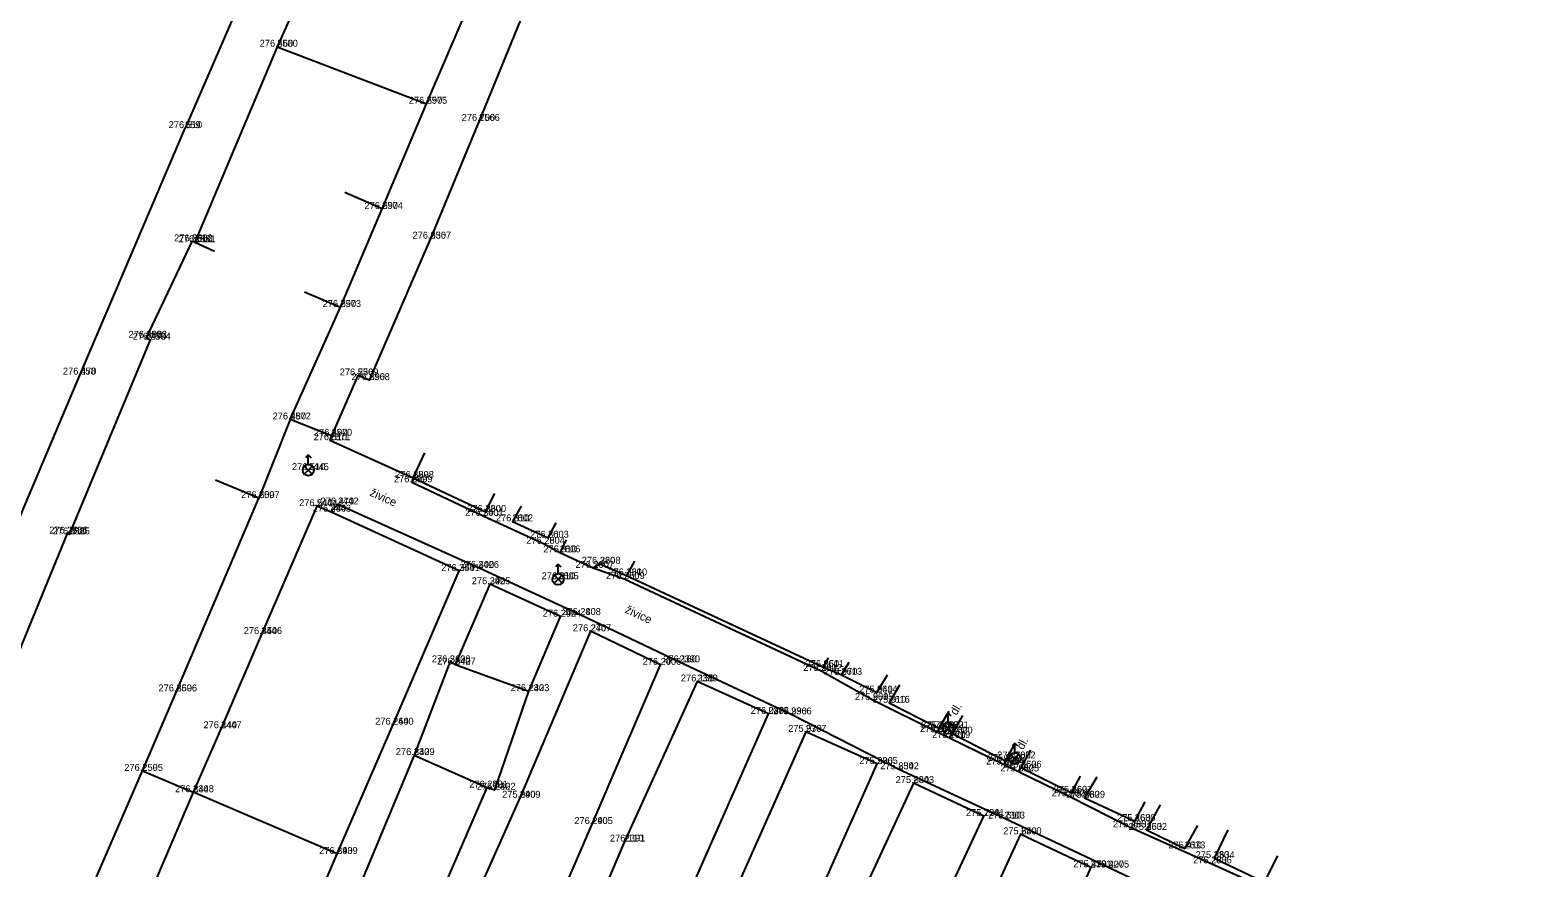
# Model space of a CAD drawing. Extents: x -776701 to -776081, y -974398 to -973771.
# Drawn here: x -776453.1 to -776398.7, y -974133.8 to -974103.6 of the extents above; entities that cross this region are included whole.
import ezdxf

# ---------------------------------------------------------------- set-up
doc = ezdxf.new("R2010")
doc.units = 0
for name, color, linetype in [('1 Body-bod', 7, 'Continuous'), ('10 Silnice-chodniky', 7, 'Continuous'), ('11 Rozhrani-nezpev zpev schody', 7, 'Continuous'), ('2 Body-cislo', 7, 'Continuous'), ('3 Body-vyska', 7, 'Continuous'), ('40 Popis-povrch', 7, 'Continuous'), ('58 Mobiliar', 7, 'Continuous'), ('7 Ploty', 7, 'Continuous')]:
    doc.layers.add(name, color=color, linetype=linetype)

msp = doc.modelspace()

# ---------------------------------------------------------------- linework, layer by layer
at = {"layer": '1 Body-bod'}
for p, q in [((-776444.22, -974104.18), (-776444.22, -974104.18)), ((-776438.83, -974106.24), (-776438.83, -974106.24)), ((-776436.93, -974106.86), (-776436.93, -974106.86)), ((-776447.55, -974107.12), (-776447.55, -974107.12)), ((-776440.43, -974110.04), (-776440.43, -974110.04)), ((-776447.3, -974111.21), (-776447.3, -974111.21)), ((-776447.19, -974111.24), (-776447.19, -974111.24)), ((-776438.69, -974111.11), (-776438.69, -974111.11)), ((-776441.94, -974113.58), (-776441.94, -974113.58)), ((-776448.95, -974114.69), (-776448.95, -974114.69)), ((-776448.81, -974114.76), (-776448.81, -974114.76)), ((-776451.33, -974116.02), (-776451.33, -974116.02)), ((-776441.31, -974116.05), (-776441.31, -974116.05)), ((-776440.9, -974116.22), (-776440.9, -974116.22)), ((-776443.75, -974117.64), (-776443.75, -974117.64)), ((-776442.26, -974118.23), (-776442.26, -974118.23)), ((-776442.32, -974118.39), (-776442.32, -974118.39)), ((-776443.1, -974119.47), (-776443.1, -974119.47)), ((-776439.36, -974119.91), (-776439.36, -974119.91)), ((-776439.31, -974119.75), (-776439.31, -974119.75)), ((-776444.88, -974120.48), (-776444.88, -974120.48)), ((-776442.79, -974120.77), (-776442.79, -974120.77)), ((-776442.3, -974120.97), (-776442.3, -974120.97)), ((-776442.03, -974120.71), (-776442.03, -974120.71)), ((-776436.7, -974120.98), (-776436.7, -974120.98)), ((-776436.79, -974121.12), (-776436.79, -974121.12)), ((-776435.73, -974121.32), (-776435.73, -974121.32)), ((-776451.81, -974121.76), (-776451.81, -974121.76)), ((-776451.73, -974121.79), (-776451.73, -974121.79)), ((-776434.58, -974122.13), (-776434.58, -974122.13)), ((-776434.44, -974121.91), (-776434.44, -974121.91)), ((-776434.02, -974122.44), (-776434.02, -974122.44)), ((-776437.65, -974123.11), (-776437.65, -974123.11)), ((-776436.96, -974123), (-776436.96, -974123)), ((-776432.81, -974123), (-776432.81, -974123)), ((-776432.57, -974122.85), (-776432.57, -974122.85)), ((-776436.55, -974123.59), (-776436.55, -974123.59)), ((-776434.08, -974123.41), (-776434.08, -974123.41)), ((-776431.7, -974123.4), (-776431.7, -974123.4)), ((-776431.61, -974123.27), (-776431.61, -974123.27)), ((-776433.99, -974124.76), (-776433.99, -974124.76)), ((-776433.28, -974124.7), (-776433.28, -974124.7)), ((-776444.79, -974125.39), (-776444.79, -974125.39)), ((-776432.91, -974125.29), (-776432.91, -974125.29)), ((-776437.99, -974126.41), (-776437.99, -974126.41)), ((-776437.8, -974126.49), (-776437.8, -974126.49)), ((-776430.38, -974126.5), (-776430.38, -974126.5)), ((-776429.7, -974126.41), (-776429.7, -974126.41)), ((-776424.58, -974126.72), (-776424.58, -974126.72)), ((-776424.5, -974126.58), (-776424.5, -974126.58)), ((-776423.85, -974126.86), (-776423.85, -974126.86)), ((-776447.86, -974127.46), (-776447.86, -974127.46)), ((-776435.14, -974127.45), (-776435.14, -974127.45)), ((-776429.06, -974127.1), (-776429.06, -974127.1)), ((-776422.57, -974127.5), (-776422.57, -974127.5)), ((-776422.72, -974127.77), (-776422.72, -974127.77)), ((-776422.13, -974127.87), (-776422.13, -974127.87)), ((-776440.04, -974128.66), (-776440.04, -974128.66)), ((-776426.49, -974128.27), (-776426.49, -974128.27)), ((-776425.67, -974128.29), (-776425.67, -974128.29)), ((-776446.25, -974128.79), (-776446.25, -974128.79)), ((-776425.14, -974128.92), (-776425.14, -974128.92)), ((-776420.37, -974128.93), (-776420.37, -974128.93)), ((-776420.33, -974128.79), (-776420.33, -974128.79)), ((-776420, -974128.79), (-776420, -974128.79)), ((-776419.95, -974129.14), (-776419.95, -974129.14)), ((-776419.86, -974128.98), (-776419.86, -974128.98)), ((-776439.28, -974129.76), (-776439.28, -974129.76)), ((-776422.56, -974130.08), (-776422.56, -974130.08)), ((-776421.8, -974130.27), (-776421.8, -974130.27)), ((-776417.98, -974130.1), (-776417.98, -974130.1)), ((-776417.93, -974129.97), (-776417.93, -974129.97)), ((-776417.59, -974129.88), (-776417.59, -974129.88)), ((-776417.37, -974130.21), (-776417.37, -974130.21)), ((-776449.09, -974130.33), (-776449.09, -974130.33)), ((-776421.25, -974130.77), (-776421.25, -974130.77)), ((-776417.46, -974130.35), (-776417.46, -974130.35)), ((-776447.25, -974131.1), (-776447.25, -974131.1)), ((-776436.64, -974130.93), (-776436.64, -974130.93)), ((-776436.36, -974131.01), (-776436.36, -974131.01)), ((-776435.46, -974131.3), (-776435.46, -974131.3)), ((-776415.61, -974131.25), (-776415.61, -974131.25)), ((-776415.54, -974131.12), (-776415.54, -974131.12)), ((-776415.08, -974131.3), (-776415.08, -974131.3)), ((-776432.85, -974132.25), (-776432.85, -974132.25)), ((-776418.71, -974131.96), (-776418.71, -974131.96)), ((-776417.97, -974132.05), (-776417.97, -974132.05)), ((-776413.4, -974132.37), (-776413.4, -974132.37)), ((-776413.26, -974132.14), (-776413.26, -974132.14)), ((-776412.84, -974132.46), (-776412.84, -974132.46)), ((-776431.68, -974132.88), (-776431.68, -974132.88)), ((-776417.37, -974132.62), (-776417.37, -974132.62)), ((-776442.06, -974133.33), (-776442.06, -974133.33)), ((-776411.46, -974133.13), (-776411.46, -974133.13)), ((-776410.4, -974133.48), (-776410.4, -974133.48)), ((-776414.85, -974133.81), (-776414.85, -974133.81)), ((-776414.21, -974133.82), (-776414.21, -974133.82)), ((-776410.5, -974133.67), (-776410.5, -974133.67))]:
    msp.add_line(p, q, dxfattribs=at)
at = {"layer": '10 Silnice-chodniky'}
msp.add_line((-776449.09, -974130.33), (-776447.25, -974131.1), dxfattribs=at)
for points in [[(-776442.26, -974118.23), (-776443.75, -974117.64), (-776444.88, -974120.48)], [(-776439.31, -974119.75), (-776439.36, -974119.91), (-776436.79, -974121.12), (-776434.58, -974122.13), (-776434.02, -974122.44)], [(-776398.71, -974141.07), (-776402.53, -974139.28), (-776406.41, -974137.48), (-776410.27, -974135.71), (-776414.21, -974133.82), (-776417.97, -974132.05), (-776421.8, -974130.27), (-776425.67, -974128.29), (-776429.7, -974126.41), (-776433.28, -974124.7), (-776436.96, -974123), (-776442.03, -974120.71), (-776442.3, -974120.97)], [(-776432.81, -974123), (-776431.7, -974123.4), (-776424.58, -974126.72), (-776422.72, -974127.77), (-776420.37, -974128.93), (-776419.95, -974129.14), (-776417.98, -974130.1), (-776417.46, -974130.35), (-776415.61, -974131.25), (-776413.4, -974132.37), (-776410.5, -974133.67), (-776408.14, -974134.74), (-776403.96, -974136.76), (-776401.68, -974137.82), (-776401.22, -974137.88)], [(-776420.33, -974128.79), (-776420.37, -974128.93)], [(-776419.95, -974129.14), (-776419.86, -974128.98)], [(-776417.93, -974129.97), (-776417.98, -974130.1)], [(-776417.46, -974130.35), (-776417.37, -974130.21)]]:
    msp.add_lwpolyline(points, dxfattribs=at)
at = {"layer": '11 Rozhrani-nezpev zpev schody'}
for points in [[(-776443.75, -974117.64), (-776441.94, -974113.58)], [(-776431.32, -974122.762), (-776431.61, -974123.27), (-776424.5, -974126.58), (-776424.32, -974126.245)]]:
    msp.add_lwpolyline(points, dxfattribs=at)
at = {"layer": '58 Mobiliar'}
for p, q in [((-776443.1, -974119.47), (-776443.243, -974119.328)), ((-776443.1, -974118.92), (-776443.2, -974119.02)), ((-776443.1, -974119.269), (-776443.1, -974118.92)), ((-776443.1, -974118.92), (-776443, -974119.02)), ((-776443.1, -974119.47), (-776442.958, -974119.328)), ((-776443.1, -974119.47), (-776443.243, -974119.613)), ((-776443.1, -974119.47), (-776443.1, -974119.47)), ((-776443.1, -974119.47), (-776442.958, -974119.613)), ((-776434.08, -974122.86), (-776434.18, -974122.96)), ((-776434.08, -974123.209), (-776434.08, -974122.86)), ((-776434.08, -974122.86), (-776433.98, -974122.96)), ((-776434.08, -974123.41), (-776434.223, -974123.268)), ((-776434.08, -974123.41), (-776434.223, -974123.552)), ((-776434.08, -974123.41), (-776433.938, -974123.268)), ((-776434.08, -974123.41), (-776434.08, -974123.41)), ((-776434.08, -974123.41), (-776433.938, -974123.552)), ((-776420, -974128.79), (-776420.142, -974128.647)), ((-776420, -974128.24), (-776420.1, -974128.34)), ((-776420, -974128.589), (-776420, -974128.24)), ((-776420, -974128.24), (-776419.9, -974128.34)), ((-776420, -974128.79), (-776419.858, -974128.647)), ((-776420, -974128.79), (-776420.142, -974128.932)), ((-776420, -974128.79), (-776420, -974128.79)), ((-776420, -974128.79), (-776419.858, -974128.932)), ((-776417.59, -974129.88), (-776417.733, -974129.738)), ((-776417.59, -974129.33), (-776417.69, -974129.43)), ((-776417.59, -974129.679), (-776417.59, -974129.33)), ((-776417.59, -974129.33), (-776417.49, -974129.43)), ((-776417.59, -974129.88), (-776417.448, -974129.738)), ((-776417.59, -974129.88), (-776417.733, -974130.022)), ((-776417.59, -974129.88), (-776417.59, -974129.88)), ((-776417.59, -974129.88), (-776417.448, -974130.022))]:
    msp.add_line(p, q, dxfattribs=at)
for centre in [(-776443.1, -974119.47), (-776434.08, -974123.41), (-776420, -974128.79), (-776417.59, -974129.88)]:
    msp.add_circle(centre, 0.202, dxfattribs=at)
at = {"layer": '7 Ploty'}
for p, q in [((-776444.22, -974104.18), (-776438.83, -974106.24)), ((-776440.43, -974110.04), (-776441.781, -974109.444)), ((-776447.19, -974111.24), (-776446.482, -974111.559)), ((-776439.31, -974119.75), (-776438.886, -974118.84)), ((-776437.8, -974126.49), (-776435.14, -974127.45)), ((-776423.85, -974126.86), (-776423.571, -974126.402)), ((-776439.28, -974129.76), (-776436.64, -974130.93)), ((-776442.06, -974133.33), (-776447.25, -974131.1))]:
    msp.add_line(p, q, dxfattribs=at)
for points in [[(-776429.948, -974094.946), (-776431.62, -974094.27), (-776433.01, -974097.62), (-776435.03, -974102.2), (-776436.93, -974106.86), (-776438.69, -974111.11), (-776440.9, -974116.22), (-776441.31, -974116.05), (-776442.26, -974118.23), (-776442.32, -974118.39), (-776439.31, -974119.75), (-776436.7, -974120.98), (-776436.365, -974120.318)], [(-776444.45, -974099.97), (-776447.55, -974107.12)], [(-776442.181, -974101.633), (-776442.94, -974101.3), (-776444.22, -974104.18), (-776447.19, -974111.24), (-776447.3, -974111.21), (-776448.95, -974114.69), (-776448.81, -974114.76), (-776451.73, -974121.79), (-776451.81, -974121.76), (-776454.79, -974129.02), (-776457.78, -974135.74), (-776459.29, -974139.32)], [(-776443.232, -974113.037), (-776441.94, -974113.58), (-776440.43, -974110.04), (-776438.83, -974106.24), (-776437.47, -974103.08), (-776439.56, -974102.11)], [(-776462.923, -974135.406), (-776463.64, -974136.81), (-776462.19, -974138.79), (-776461.12, -974138.67), (-776459.04, -974133.94), (-776456.22, -974127.33), (-776453.9, -974122.37), (-776453.7, -974121.62), (-776451.33, -974116.02), (-776447.55, -974107.12)], [(-776458.16, -974144.19), (-776455.54, -974145.34), (-776452.99, -974139.44), (-776450.85, -974134.41), (-776449.09, -974130.33), (-776447.86, -974127.46), (-776444.88, -974120.48), (-776446.452, -974119.83)], [(-776451.04, -974154.17), (-776448.3, -974147.96), (-776446.55, -974144.18), (-776444.55, -974139.17), (-776442.06, -974133.33), (-776440.04, -974128.66), (-776437.65, -974123.11), (-776442.3, -974120.97), (-776442.79, -974120.77), (-776444.79, -974125.39), (-776446.25, -974128.79), (-776447.25, -974131.1), (-776449, -974135.19), (-776450.92, -974139.78), (-776452.5, -974143.44), (-776454.8, -974148.9), (-776451.04, -974154.17)], [(-776435.412, -974120.773), (-776435.73, -974121.32), (-776434.44, -974121.91), (-776434.149, -974121.374)], [(-776433.787, -974121.985), (-776434.02, -974122.44), (-776432.81, -974123), (-776432.57, -974122.85), (-776431.61, -974123.27)], [(-776447.07, -974155.3), (-776445.59, -974151.84), (-776442.69, -974145.03), (-776439.96, -974138.63), (-776438.39, -974134.96), (-776436.64, -974130.93), (-776436.36, -974131.01), (-776435.14, -974127.45), (-776433.99, -974124.76), (-776436.55, -974123.59), (-776437.8, -974126.49), (-776437.99, -974126.41), (-776439.28, -974129.76), (-776441.8, -974135.82), (-776443.28, -974139.15), (-776445.22, -974143.81), (-776446.87, -974148.54), (-776449.69, -974154.17), (-776447.07, -974155.3)], [(-776446.33, -974160.71), (-776444.92, -974160.33), (-776441.9, -974153.35), (-776439.23, -974147.15), (-776436.77, -974141.28), (-776434.98, -974137.19), (-776432.85, -974132.25), (-776430.38, -974126.5), (-776432.91, -974125.29), (-776435.46, -974131.3), (-776437.44, -974135.73), (-776439.37, -974140.27), (-776441.54, -974145.34), (-776444.49, -974152.23), (-776447.43, -974159.14), (-776446.33, -974160.71)], [(-776424.5, -974126.58), (-776423.85, -974126.86), (-776422.57, -974127.5), (-776422.185, -974126.859)], [(-776439.56, -974158.15), (-776437.04, -974152.46), (-776434.06, -974145.6), (-776431.99, -974141), (-776430.07, -974136.39), (-776426.49, -974128.27), (-776429.06, -974127.1), (-776431.68, -974132.88), (-776433.64, -974137.49), (-776434.71, -974139.78), (-776435.69, -974142.11), (-776435.61, -974142.14), (-776438.23, -974147.96), (-776439.66, -974151.35), (-776442.17, -974157.05), (-776439.56, -974158.15)], [(-776421.751, -974127.239), (-776422.13, -974127.87), (-776420.33, -974128.79), (-776419.965, -974128.176)], [(-776419.482, -974128.328), (-776419.86, -974128.98), (-776417.93, -974129.97), (-776417.626, -974129.428)], [(-776440.88, -974166.89), (-776439.33, -974166.93), (-776437.12, -974162.12), (-776435.56, -974158.67), (-776434.03, -974155.26), (-776432.94, -974153.04), (-776430.36, -974147.33), (-776428.58, -974143.53), (-776427.15, -974140.36), (-776425.14, -974135.87), (-776422.56, -974130.08), (-776425.14, -974128.92), (-776428.71, -974136.96), (-776429.79, -974139.27), (-776432.93, -974146.23), (-776435.83, -974152.43), (-776438.66, -974158.67), (-776441.87, -974165.77), (-776440.88, -974166.89)], [(-776417.032, -974129.587), (-776417.37, -974130.21), (-776415.54, -974131.12), (-776415.217, -974130.526)], [(-776435.48, -974167.97), (-776433.12, -974162.99), (-776431.7, -974159.93), (-776430.86, -974158.2), (-776428.74, -974153.61), (-776428.34, -974152.77), (-776428.12, -974152.25), (-776426.6, -974149.09), (-776424.5, -974144.5), (-776422.38, -974140), (-776420.34, -974135.44), (-776418.71, -974131.96), (-776421.25, -974130.77), (-776423.92, -974136.54), (-776426.01, -974141.1), (-776428.12, -974145.63), (-776430.25, -974150.09), (-776432.34, -974154.68), (-776434.51, -974159.35), (-776436.78, -974164.14), (-776438.04, -974166.77), (-776435.48, -974167.97)], [(-776414.628, -974130.557), (-776415.08, -974131.3), (-776413.26, -974132.14), (-776412.888, -974131.442)], [(-776412.34, -974131.552), (-776412.84, -974132.46), (-776411.46, -974133.13), (-776410.984, -974132.298)], [(-776409.898, -974132.463), (-776410.4, -974133.48), (-776408.58, -974134.35), (-776408.099, -974133.401)], [(-776418.42, -974134.89), (-776417.37, -974132.62), (-776414.85, -974133.81), (-776415.87, -974136.09), (-776418.42, -974134.89)]]:
    msp.add_lwpolyline(points, dxfattribs=at)

# ---------------------------------------------------------------- texts
at = {"layer": '2 Body-cislo'}
for s, p in [('2580', (-776444.22, -974104.18)), ('2575', (-776438.83, -974106.24)), ('659', (-776447.55, -974107.12)), ('2566', (-776436.93, -974106.86)), ('2574', (-776440.43, -974110.04)), ('2582', (-776447.3, -974111.21)), ('2581', (-776447.19, -974111.24)), ('2567', (-776438.69, -974111.11)), ('2573', (-776441.94, -974113.58)), ('2583', (-776448.95, -974114.69)), ('2584', (-776448.81, -974114.76)), ('658', (-776451.33, -974116.02)), ('2569', (-776441.31, -974116.05)), ('2568', (-776440.9, -974116.22)), ('2572', (-776443.75, -974117.64)), ('2571', (-776442.32, -974118.39)), ('2570', (-776442.26, -974118.23)), ('2445', (-776443.1, -974119.47)), ('2599', (-776439.36, -974119.91)), ('2598', (-776439.31, -974119.75)), ('2597', (-776444.88, -974120.48)), ('2444', (-776442.79, -974120.77)), ('2442', (-776442.03, -974120.71)), ('2443', (-776442.3, -974120.97)), ('2601', (-776436.79, -974121.12)), ('2600', (-776436.7, -974120.98)), ('2586', (-776451.81, -974121.76)), ('2585', (-776451.73, -974121.79)), ('2602', (-776435.73, -974121.32)), ('2604', (-776434.58, -974122.13)), ('2603', (-776434.44, -974121.91)), ('2606', (-776434.02, -974122.44)), ('2608', (-776432.57, -974122.85)), ('2441', (-776437.65, -974123.11)), ('2426', (-776436.96, -974123)), ('2605', (-776434.08, -974123.41)), ('2607', (-776432.81, -974123)), ('2609', (-776431.7, -974123.4)), ('2610', (-776431.61, -974123.27)), ('2425', (-776436.55, -974123.59)), ('2424', (-776433.99, -974124.76)), ('2408', (-776433.28, -974124.7)), ('2446', (-776444.79, -974125.39)), ('2407', (-776432.91, -974125.29)), ('2428', (-776437.99, -974126.41)), ('2427', (-776437.8, -974126.49)), ('2406', (-776430.38, -974126.5)), ('2390', (-776429.7, -974126.41)), ('2612', (-776424.58, -974126.72)), ('2611', (-776424.5, -974126.58)), ('2389', (-776429.06, -974127.1)), ('2613', (-776423.85, -974126.86)), ('2596', (-776447.86, -974127.46)), ('2423', (-776435.14, -974127.45)), ('2615', (-776422.72, -974127.77)), ('2614', (-776422.57, -974127.5)), ('2388', (-776426.49, -974128.27)), ('2366', (-776425.67, -974128.29)), ('2616', (-776422.13, -974127.87)), ('2447', (-776446.25, -974128.79)), ('2440', (-776440.04, -974128.66)), ('2367', (-776425.14, -974128.92)), ('2618', (-776420.37, -974128.93)), ('2617', (-776420.33, -974128.79)), ('2621', (-776420, -974128.79)), ('2619', (-776419.95, -974129.14)), ('2620', (-776419.86, -974128.98)), ('2429', (-776439.28, -974129.76)), ('2623', (-776417.93, -974129.97)), ('2622', (-776417.59, -974129.88)), ('2595', (-776449.09, -974130.33)), ('2365', (-776422.56, -974130.08)), ('2342', (-776421.8, -974130.27)), ('2624', (-776417.98, -974130.1)), ('2625', (-776417.46, -974130.35)), ('2626', (-776417.37, -974130.21)), ('2448', (-776447.25, -974131.1)), ('2421', (-776436.64, -974130.93)), ('2422', (-776436.36, -974131.01)), ('2343', (-776421.25, -974130.77)), ('2409', (-776435.46, -974131.3)), ('2628', (-776415.61, -974131.25)), ('2627', (-776415.54, -974131.12)), ('2629', (-776415.08, -974131.3)), ('2341', (-776418.71, -974131.96)), ('2303', (-776417.97, -974132.05)), ('2630', (-776413.26, -974132.14)), ('2405', (-776432.85, -974132.25)), ('2300', (-776417.37, -974132.62)), ('2631', (-776413.4, -974132.37)), ('2632', (-776412.84, -974132.46)), ('2391', (-776431.68, -974132.88)), ('2633', (-776411.46, -974133.13)), ('2439', (-776442.06, -974133.33)), ('2301', (-776414.85, -974133.81)), ('2275', (-776414.21, -974133.82)), ('2636', (-776410.5, -974133.67)), ('2634', (-776410.4, -974133.48))]:
    msp.add_text(s, height=0.25, dxfattribs=at).set_placement(p)
at = {"layer": '3 Body-vyska'}
for s, p in [('276.460', (-776444.854, -974104.18)), ('276.590', (-776439.471, -974106.24)), ('276.510', (-776448.139, -974107.12)), ('276.700', (-776437.562, -974106.86)), ('276.590', (-776441.071, -974110.04)), ('276.500', (-776447.945, -974111.21)), ('276.510', (-776447.779, -974111.24)), ('276.630', (-776439.337, -974111.11)), ('276.590', (-776442.581, -974113.58)), ('276.480', (-776449.588, -974114.69)), ('276.470', (-776449.438, -974114.76)), ('276.470', (-776451.958, -974116.02)), ('276.530', (-776441.963, -974116.05)), ('276.590', (-776441.541, -974116.22)), ('276.480', (-776444.388, -974117.64)), ('276.510', (-776442.909, -974118.39)), ('276.490', (-776442.894, -974118.23)), ('276.510', (-776443.689, -974119.47)), ('276.390', (-776440.007, -974119.91)), ('276.380', (-776439.961, -974119.75)), ('276.500', (-776445.525, -974120.48)), ('276.540', (-776443.431, -974120.77)), ('276.470', (-776442.658, -974120.71)), ('276.480', (-776442.938, -974120.97)), ('276.340', (-776437.437, -974121.12)), ('276.330', (-776437.359, -974120.98)), ('276.270', (-776452.449, -974121.76)), ('276.310', (-776452.325, -974121.79)), ('276.310', (-776436.325, -974121.32)), ('276.280', (-776435.229, -974122.13)), ('276.300', (-776435.091, -974121.91)), ('276.310', (-776434.615, -974122.44)), ('276.320', (-776433.227, -974122.85)), ('276.350', (-776438.303, -974123.11)), ('276.400', (-776437.598, -974123)), ('276.310', (-776434.675, -974123.41)), ('276.290', (-776433.455, -974123)), ('276.250', (-776432.352, -974123.4)), ('276.230', (-776432.267, -974123.27)), ('276.390', (-776437.197, -974123.59)), ('276.290', (-776434.635, -974124.76)), ('276.280', (-776433.929, -974124.7)), ('276.450', (-776445.431, -974125.39)), ('276.270', (-776433.549, -974125.29)), ('276.360', (-776438.637, -974126.41)), ('276.340', (-776438.447, -974126.49)), ('276.200', (-776431.029, -974126.5)), ('276.160', (-776430.283, -974126.41)), ('275.930', (-776425.233, -974126.72)), ('276.050', (-776425.145, -974126.58)), ('276.150', (-776429.649, -974127.1)), ('275.970', (-776424.485, -974126.86)), ('276.360', (-776448.507, -974127.46)), ('276.230', (-776435.797, -974127.45)), ('275.900', (-776423.365, -974127.77)), ('275.940', (-776423.211, -974127.5)), ('276.040', (-776427.128, -974128.27)), ('275.990', (-776426.311, -974128.29)), ('275.910', (-776422.719, -974127.87)), ('276.440', (-776446.884, -974128.79)), ('276.260', (-776440.685, -974128.66)), ('275.970', (-776425.775, -974128.92)), ('275.800', (-776421.019, -974128.93)), ('275.800', (-776420.979, -974128.79)), ('275.830', (-776420.657, -974128.79)), ('275.770', (-776420.579, -974129.14)), ('275.800', (-776420.509, -974128.98)), ('276.330', (-776439.939, -974129.76)), ('275.690', (-776418.571, -974129.97)), ('275.700', (-776418.229, -974129.88)), ('276.250', (-776449.742, -974130.33)), ('275.900', (-776423.205, -974130.08)), ('275.850', (-776422.452, -974130.27)), ('275.650', (-776418.628, -974130.1)), ('275.630', (-776418.113, -974130.35)), ('275.650', (-776418.018, -974130.21)), ('276.330', (-776447.909, -974131.1)), ('276.280', (-776437.289, -974130.93)), ('276.230', (-776437.017, -974131.01)), ('275.860', (-776421.895, -974130.77)), ('275.990', (-776436.101, -974131.3)), ('275.550', (-776416.264, -974131.25)), ('275.560', (-776416.188, -974131.12)), ('275.530', (-776415.74, -974131.3)), ('275.720', (-776419.356, -974131.96)), ('275.610', (-776418.559, -974132.05)), ('275.460', (-776413.901, -974132.14)), ('276.290', (-776433.495, -974132.25)), ('275.640', (-776418.011, -974132.62)), ('275.430', (-776414.053, -974132.37)), ('275.450', (-776413.488, -974132.46)), ('276.110', (-776432.211, -974132.88)), ('275.410', (-776412.049, -974133.13)), ('276.390', (-776442.707, -974133.33)), ('275.470', (-776415.485, -974133.81)), ('275.400', (-776414.855, -974133.82)), ('275.280', (-776411.155, -974133.67)), ('275.330', (-776411.066, -974133.48))]:
    msp.add_text(s, height=0.25, dxfattribs=at).set_placement(p)
at = {"layer": '40 Popis-povrch'}
for s, rotation, p in [('živice', 335.6853, (-776440.905, -974120.381)), ('živice', 335.1648, (-776431.689, -974124.605)), ('dl.', 59.8873, (-776419.695, -974128.345)), ('dl.', 61.5099, (-776417.294, -974129.59))]:
    msp.add_text(s, height=0.3, rotation=rotation, dxfattribs=at).set_placement(p)

doc.saveas('drawing.dxf')
